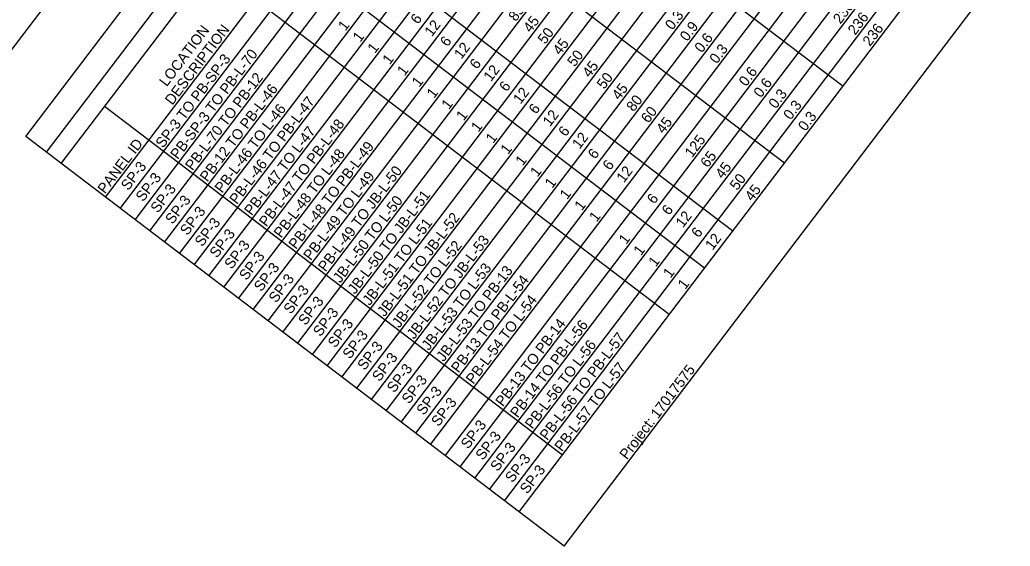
# Model space of a CAD drawing. Extents: x 1289840 to 1300285, y 220865 to 232461.
# Drawn here: x 1299156 to 1299781, y 230983 to 231315 of the extents above; entities that cross this region are included whole.
import ezdxf

# ---------------------------------------------------------------- set-up
doc = ezdxf.new("R2010")
doc.units = 0
doc.layers.add('Default', color=7, linetype='Continuous')
doc.layers.add('R_No Plot', color=7, linetype='Continuous')

msp = doc.modelspace()

# ---------------------------------------------------------------- linework, layer by layer
at = {"layer": 'Default'}
for p, q in [((1299128.21, 231265.73), (1299646.6, 231947.46)), ((1299160.21, 231241.4), (1299678.61, 231923.13)), ((1299173.25, 231231.49), (1299691.64, 231913.21)), ((1299182.56, 231224.4), (1299700.96, 231906.13)), ((1299210.5, 231203.16), (1299728.9, 231884.89)), ((1299219.81, 231196.08), (1299738.21, 231877.8)), ((1299229.13, 231188.99), (1299747.52, 231870.72)), ((1299238.44, 231181.91), (1299756.84, 231863.64)), ((1299247.75, 231174.83), (1299766.15, 231856.56)), ((1299257.07, 231167.75), (1299775.46, 231849.48)), ((1299266.38, 231160.67), (1299784.78, 231842.4)), ((1299275.69, 231153.58), (1299794.09, 231835.31)), ((1299285.01, 231146.5), (1299803.4, 231828.23)), ((1299294.32, 231139.42), (1299812.72, 231821.15)), ((1299303.63, 231132.34), (1299822.03, 231814.07)), ((1299312.95, 231125.26), (1299831.34, 231806.99)), ((1299322.26, 231118.17), (1299840.66, 231799.9)), ((1299331.57, 231111.09), (1299849.97, 231792.82)), ((1299340.89, 231104.01), (1299859.28, 231785.74)), ((1299350.2, 231096.93), (1299868.6, 231778.66)), ((1299359.51, 231089.85), (1299877.91, 231771.58)), ((1299368.83, 231082.77), (1299887.22, 231764.49)), ((1299378.14, 231075.68), (1299896.54, 231757.41)), ((1299387.45, 231068.6), (1299905.85, 231750.33)), ((1299396.77, 231061.52), (1299915.16, 231743.25)), ((1299406.08, 231054.44), (1299924.47, 231736.17)), ((1299415.39, 231047.36), (1299933.79, 231729.08)), ((1299424.7, 231040.27), (1299943.1, 231722)), ((1299434.02, 231033.19), (1299952.41, 231714.92)), ((1299443.33, 231026.11), (1299961.73, 231707.84)), ((1299452.64, 231019.03), (1299971.04, 231700.76)), ((1299461.96, 231011.95), (1299980.35, 231693.67)), ((1299471.27, 231004.86), (1299989.67, 231686.59)), ((1299499.68, 230983.26), (1300018.07, 231664.99)), ((1299675.23, 231273.09), (1299386.52, 231492.62)), ((1299638.4, 231224.66), (1299349.69, 231444.2)), ((1299605.83, 231181.82), (1299317.12, 231401.35)), ((1299588.12, 231158.53), (1299299.41, 231378.07)), ((1299565.81, 231129.2), (1299277.1, 231348.74)), ((1299498.54, 231040.72), (1299209.83, 231260.26)), ((1299499.68, 230983.26), (1299160.21, 231241.4))]:
    msp.add_line(p, q, dxfattribs=at)
at = {"layer": 'R_No Plot'}
msp.add_line((1299160.21, 231241.4), (1299160.21, 231241.4), dxfattribs=at)

# ---------------------------------------------------------------- texts
at = {"layer": 'Default'}
for s, p in [('236', (1299673.74, 231311.97)), ('85', (1299469.13, 231313.5)), ('0.3', (1299567.89, 231308.07)), ('1', (1299361.71, 231307.55)), ('6', (1299407.44, 231311.72)), ('12', (1299416.2, 231303.92)), ('45', (1299478.44, 231306.42)), ('236', (1299683.05, 231304.88)), ('LOCATION', (1299249.09, 231272.44)), ('DESCRIPTION', (1299252.66, 231260.78)), ('50', (1299487.58, 231299.11)), ('0.9', (1299577.19, 231300.97)), ('236', (1299692.37, 231297.8)), ('1', (1299371.03, 231300.47)), ('6', (1299426.06, 231297.56)), ('45', (1299497.07, 231292.25)), ('0.6', (1299586.41, 231293.76)), ('PB-SP-3 TO PB-L-70', (1299256.05, 231226.58)), ('1', (1299380.34, 231293.38)), ('12', (1299434.83, 231289.75)), ('50', (1299506.21, 231284.94)), ('0.3', (1299595.83, 231286.82)), ('SP-3 TO PB-SP-3', (1299246.74, 231233.66)), ('1', (1299389.65, 231286.3)), ('6', (1299444.69, 231283.39)), ('45', (1299515.69, 231278.09)), ('1', (1299398.97, 231279.22)), ('12', (1299453.45, 231275.59)), ('0.6', (1299614.35, 231272.52)), ('PB-L-70 TO PB-12', (1299265.36, 231219.5)), ('1', (1299408.28, 231272.14)), ('6', (1299463.32, 231269.23)), ('50', (1299524.83, 231270.78)), ('0.6', (1299623.66, 231265.43)), ('PB-12 TO PB-L-46', (1299274.68, 231212.42)), ('1', (1299417.59, 231265.06)), ('12', (1299472.08, 231261.42)), ('45', (1299534.32, 231263.93)), ('0.3', (1299633.08, 231258.5)), ('PB-L-46 TO PB-L-47', (1299293.3, 231198.25)), ('1', (1299426.91, 231257.97)), ('80', (1299543.46, 231256.62)), ('0.3', (1299642.4, 231251.42)), ('PB-L-46 TO L-46', (1299283.99, 231205.33)), ('6', (1299481.94, 231255.07)), ('12', (1299490.71, 231247.26)), ('60', (1299552.68, 231249.41)), ('PB-L-47 TO PB-L-48', (1299311.93, 231184.09)), ('1', (1299436.22, 231250.89)), ('45', (1299562.26, 231242.68)), ('0.3', (1299651.71, 231244.33)), ('PB-L-47 TO L-47', (1299302.62, 231191.17)), ('1', (1299445.53, 231243.81)), ('6', (1299500.57, 231240.9)), ('PANEL ID', (1299210.16, 231204.89)), ('1', (1299454.85, 231236.73)), ('12', (1299509.33, 231233.1)), ('125', (1299580.23, 231227.65)), ('PB-L-48 TO L-48', (1299321.24, 231177.01)), ('PB-L-48 TO PB-L-49', (1299330.56, 231169.92)), ('1', (1299464.16, 231229.65)), ('6', (1299519.2, 231226.74)), ('1', (1299473.47, 231222.56)), ('6', (1299528.51, 231219.66)), ('65', (1299590.11, 231221.31)), ('SP-3', (1299224.87, 231206.94)), ('PB-L-49 TO JB-L-50', (1299349.18, 231155.76)), ('1', (1299482.79, 231215.48)), ('12', (1299537.27, 231211.85)), ('45', (1299599.51, 231214.35)), ('SP-3', (1299234.19, 231199.86)), ('PB-L-49 TO L-49', (1299339.87, 231162.84)), ('1', (1299492.1, 231208.4)), ('50', (1299608.65, 231207.04)), ('SP-3', (1299243.5, 231192.78)), ('45', (1299618.14, 231200.19)), ('SP-3', (1299252.81, 231185.7)), ('JB-L-50 TO L-50', (1299358.5, 231148.68)), ('JB-L-50 TO JB-L-51', (1299367.81, 231141.6)), ('1', (1299501.41, 231201.32)), ('6', (1299556.45, 231198.41)), ('SP-3', (1299262.13, 231178.62)), ('1', (1299510.73, 231194.24)), ('6', (1299565.76, 231191.33)), ('SP-3', (1299271.44, 231171.53)), ('JB-L-51 TO L-51', (1299377.12, 231134.52)), ('JB-L-51 TO JB-L-52', (1299386.44, 231127.43)), ('1', (1299520.04, 231187.15)), ('12', (1299574.53, 231183.52)), ('SP-3', (1299280.75, 231164.45)), ('6', (1299584.39, 231177.17)), ('JB-L-52 TO JB-L-53', (1299405.06, 231113.27)), ('1', (1299538.66, 231172.99)), ('12', (1299593.15, 231169.36)), ('SP-3', (1299290.07, 231157.37)), ('JB-L-52 TO L-52', (1299395.75, 231120.35)), ('1', (1299547.98, 231165.91)), ('SP-3', (1299299.38, 231150.29)), ('1', (1299557.29, 231158.83)), ('SP-3', (1299308.69, 231143.21)), ('JB-L-53 TO L-53', (1299414.37, 231106.19)), ('JB-L-53 TO PB-13', (1299423.69, 231099.11)), ('1', (1299566.6, 231151.74)), ('SP-3', (1299318.01, 231136.12)), ('PB-13 TO PB-L-54', (1299433, 231092.02)), ('SP-3', (1299327.32, 231129.04)), ('1', (1299575.92, 231144.66)), ('SP-3', (1299336.63, 231121.96)), ('PB-L-54 TO L-54', (1299442.31, 231084.94)), ('SP-3', (1299345.95, 231114.88)), ('PB-13 TO PB-14', (1299460.94, 231070.78)), ('SP-3', (1299355.26, 231107.8)), ('PB-14 TO PB-L-56', (1299470.25, 231063.7)), ('SP-3', (1299364.57, 231100.71)), ('PB-L-56 TO PB-L-57', (1299488.88, 231049.53)), ('SP-3', (1299373.89, 231093.63)), ('PB-L-56 TO L-56', (1299479.57, 231056.61)), ('SP-3', (1299383.2, 231086.55)), ('SP-3', (1299392.51, 231079.47)), ('PB-L-57 TO L-57', (1299498.19, 231042.45)), ('Project: 17017575', (1299539.17, 231037.39)), ('SP-3', (1299401.83, 231072.39)), ('SP-3', (1299411.14, 231065.3)), ('SP-3', (1299420.45, 231058.22)), ('SP-3', (1299439.08, 231044.06)), ('SP-3', (1299448.39, 231036.98)), ('SP-3', (1299457.7, 231029.89)), ('SP-3', (1299467.02, 231022.81)), ('SP-3', (1299476.33, 231015.73))]:
    msp.add_text(s, height=6.6, rotation=52.75013, dxfattribs=at).set_placement(p)

doc.saveas('drawing.dxf')
